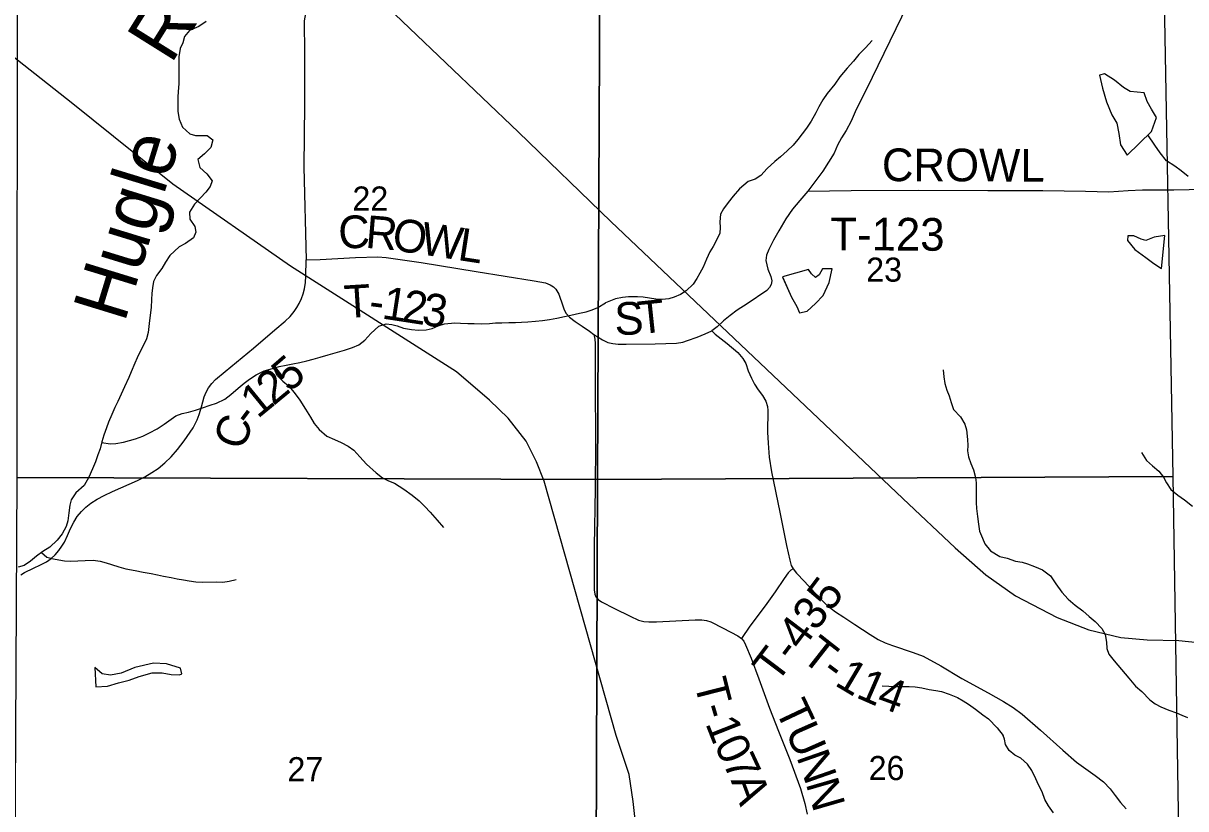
# Model space of a CAD drawing. Extents: x 0 to 34, y 0 to 22.
# Drawn here: x 3.267 to 5.287, y 18.409 to 19.775 of the extents above; entities that cross this region are included whole.
import ezdxf

# ---------------------------------------------------------------- set-up
doc = ezdxf.new("R2010")
doc.units = 0
doc.layers.add('Default', color=7, linetype='Continuous')

msp = doc.modelspace()

# ---------------------------------------------------------------- linework, layer by layer
at = {"layer": 'Default'}
for points in [[(2.781, 20.587), (3.2581, 20.2961), (3.5691, 20.1012), (3.6469, 20.0395), (3.6858, 20.0076), (4.1277, 19.5854), (4.2882, 19.4298), (4.7959, 18.9483), (4.8867, 18.8627), (4.9397, 18.8161), (4.9914, 18.7791), (5.0638, 18.7415), (5.1188, 18.7201), (5.1744, 18.7071), (5.2205, 18.7028), (5.2754, 18.7016), (5.3374, 18.6952), (5.4602, 18.6836), (5.597, 18.6827), (5.698, 18.6656), (5.9841, 18.6456), (6.1617, 18.6371), (6.2768, 18.6314)], [(3.7949, 19.8708), (3.7793, 19.8505), (3.7736, 19.8419), (3.7693, 19.8339), (3.7648, 19.8223), (3.7614, 19.8101), (3.7555, 19.779), (3.7561, 19.722), (3.7559, 19.6337), (3.7546, 19.5245), (3.759, 19.3634)], [(4.8036, 19.8068), (4.732, 19.6587), (4.7148, 19.6248), (4.7062, 19.6042), (4.6971, 19.5879), (4.6892, 19.5753), (4.6821, 19.5627), (4.6765, 19.549), (4.6569, 19.5177), (4.6426, 19.4987), (4.6308, 19.4826)], [(3.5852, 19.7778), (3.5721, 19.7689), (3.5562, 19.7618), (3.5473, 19.7514), (3.5444, 19.7407), (3.5396, 19.7304), (3.5375, 19.7163), (3.5373, 19.7053), (3.5378, 19.6939), (3.5376, 19.6825), (3.5374, 19.6692), (3.5361, 19.6559), (3.5359, 19.646), (3.5356, 19.635), (3.5358, 19.6213), (3.5383, 19.6077), (3.5438, 19.5937), (3.5565, 19.5825), (3.5664, 19.5796), (3.5766, 19.5794), (3.5865, 19.5795), (3.5968, 19.5717), (3.5932, 19.5587), (3.582, 19.5475), (3.5707, 19.5375), (3.5743, 19.5239), (3.5862, 19.513), (3.5955, 19.5006), (3.5922, 19.4907), (3.5844, 19.4807), (3.5751, 19.4711), (3.565, 19.4603), (3.5561, 19.4465)], [(4.3327, 18.3689), (4.327, 18.4219), (4.32, 18.469), (4.2976, 18.5366), (4.1726, 18.9789), (4.1592, 19.0123), (4.141, 19.0483), (4.1098, 19.0881), (4.0777, 19.1194), (4.02, 19.1687), (3.7318, 19.3523), (3.5272, 19.4951), (3.3531, 19.6346), (3.2123, 19.745)], [(4.7427, 19.7448), (4.7311, 19.7317), (4.7192, 19.7201), (4.7099, 19.7085), (4.6987, 19.6965), (4.6864, 19.6814), (4.6775, 19.6687), (4.6642, 19.6525), (4.6568, 19.6413), (4.6498, 19.6294), (4.6446, 19.6191), (4.6362, 19.6041), (4.6284, 19.5921), (4.6206, 19.5821), (4.6132, 19.5725), (4.605, 19.5628), (4.5949, 19.5531), (4.583, 19.5422), (4.5732, 19.5341), (4.5598, 19.522), (4.549, 19.51), (4.5392, 19.5038), (4.5267, 19.4997), (4.5121, 19.4869), (4.501, 19.4738), (4.4924, 19.4633), (4.4843, 19.4522), (4.4791, 19.4426), (4.4775, 19.4292), (4.4784, 19.4194), (4.4775, 19.4095), (4.472, 19.3976), (4.4661, 19.3868), (4.4602, 19.3772), (4.4544, 19.3646), (4.4486, 19.3508), (4.4431, 19.3404), (4.4379, 19.3308), (4.4316, 19.3208), (4.4193, 19.3095), (4.4092, 19.3029), (4.3986, 19.2985), (4.3888, 19.2956), (4.3774, 19.2947), (4.3663, 19.2952), (4.3553, 19.2969), (4.3442, 19.2982), (4.3347, 19.2988), (4.3191, 19.2992), (4.3084, 19.2979), (4.2963, 19.2954), (4.2792, 19.2885)], [(5.2277, 19.5867), (5.2368, 19.6105), (5.2278, 19.6251), (5.2206, 19.6387), (5.215, 19.6538), (5.191, 19.6559), (5.1791, 19.6629), (5.1633, 19.6755), (5.1459, 19.6866), (5.1376, 19.6845), (5.143, 19.6618), (5.1495, 19.638), (5.1587, 19.6154), (5.1674, 19.6011), (5.1711, 19.583), (5.1738, 19.5633), (5.1856, 19.5453)], [(5.1856, 19.5453), (5.2277, 19.5867)], [(5.2916, 19.5082), (5.2797, 19.5178), (5.2685, 19.526), (5.2542, 19.5356), (5.2429, 19.5494), (5.2339, 19.5629), (5.2217, 19.5808)], [(4.6308, 19.4826), (4.7057, 19.484), (4.8231, 19.4843), (4.9433, 19.4838), (5.0389, 19.4839), (5.113, 19.483), (5.1538, 19.4816), (5.1871, 19.4836), (5.2124, 19.4853), (5.2667, 19.4853), (5.346, 19.4867), (5.3931, 19.4869), (5.4678, 19.4898), (5.5083, 19.4915), (5.5457, 19.4927), (5.5977, 19.493), (5.701, 19.4923), (5.8241, 19.4952), (5.8521, 19.4965), (5.9483, 19.4963), (5.9584, 19.4952)], [(4.6308, 19.4826), (4.6168, 19.4665), (4.6041, 19.4516), (4.5922, 19.4347), (4.58, 19.414), (4.5707, 19.3974), (4.563, 19.3816), (4.5588, 19.3717), (4.5574, 19.3621), (4.5609, 19.3474), (4.5666, 19.3343), (4.568, 19.327), (4.5671, 19.3207), (4.5643, 19.3153), (4.5595, 19.3102), (4.5253, 19.2871), (4.5081, 19.2757), (4.4958, 19.2666), (4.4842, 19.2572), (4.473, 19.2467), (4.464, 19.2398)], [(3.5561, 19.4465), (3.5566, 19.4343), (3.5655, 19.4211), (3.5672, 19.4113), (3.5628, 19.4017), (3.5489, 19.392), (3.5383, 19.3858), (3.5219, 19.3711), (3.5141, 19.3592), (3.5078, 19.3485), (3.4988, 19.3362), (3.4937, 19.3255), (3.4915, 19.3149), (3.4909, 19.3046), (3.4903, 19.2947), (3.4894, 19.2803), (3.4877, 19.2669), (3.486, 19.2525), (3.4843, 19.2369), (3.4814, 19.2258), (3.4763, 19.2151), (3.4707, 19.2051), (3.4652, 19.1933), (3.4608, 19.1837), (3.4549, 19.1688), (3.4509, 19.1589), (3.4431, 19.1424), (3.4314, 19.1172), (3.4262, 19.1069), (3.4211, 19.0946), (3.4155, 19.0813), (3.4119, 19.0713), (3.4075, 19.0587), (3.4039, 19.0469), (3.401, 19.0351), (3.3966, 19.0244), (3.393, 19.0122), (3.3875, 18.9999), (3.3809, 18.9854), (3.3731, 18.9712), (3.3585, 18.9585), (3.3507, 18.9462), (3.3482, 18.9367), (3.3465, 18.9237), (3.3447, 18.91), (3.3419, 18.8997), (3.3348, 18.8871), (3.3259, 18.876), (3.3132, 18.864), (3.3011, 18.8562), (3.2902, 18.8485), (3.2797, 18.8396), (3.2685, 18.8318), (3.2583, 18.8294)], [(5.251, 19.4056), (5.2324, 19.4029), (5.2181, 19.3969), (5.2097, 19.3994), (5.197, 19.4049), (5.1867, 19.4051), (5.1861, 19.3971), (5.199, 19.3814), (5.2183, 19.3677), (5.2322, 19.3569), (5.2453, 19.3481)], [(5.2453, 19.3481), (5.251, 19.4056)], [(3.2631, 18.816), (3.2692, 18.8197), (3.2847, 18.8274), (3.2974, 18.8331), (3.3075, 18.8384), (3.3155, 18.8442), (3.3226, 18.8509), (3.3292, 18.8582), (3.3344, 18.8656), (3.3386, 18.8729), (3.3443, 18.8843), (3.3493, 18.8962), (3.3548, 18.9074), (3.361, 18.9173), (3.3684, 18.926), (3.3761, 18.9334), (3.3849, 18.9403), (3.3958, 18.9473), (3.4078, 18.9539), (3.4222, 18.9608), (3.4656, 18.98), (3.4783, 18.9864), (3.4907, 18.9935), (3.5016, 19.0009), (3.5135, 19.0104), (3.5244, 19.0207), (3.5354, 19.0335), (3.5469, 19.0489), (3.557, 19.0636), (3.5622, 19.0715), (3.566, 19.0782), (3.5693, 19.0854), (3.5729, 19.0947), (3.5768, 19.1078), (3.5818, 19.1254), (3.5851, 19.1335), (3.589, 19.1408), (3.5947, 19.1486), (3.6012, 19.1552), (3.6182, 19.1694), (3.6671, 19.2099), (3.7044, 19.2416), (3.7223, 19.2567), (3.7309, 19.2651), (3.7379, 19.2736), (3.7424, 19.2804), (3.7465, 19.2872), (3.7507, 19.296), (3.7537, 19.3044), (3.7559, 19.3127), (3.7578, 19.3237), (3.7585, 19.3351), (3.759, 19.3634)], [(3.759, 19.3634), (3.7832, 19.3638), (3.8443, 19.3673), (3.8834, 19.3683), (3.8981, 19.3675), (3.9588, 19.3587), (4.0545, 19.3432), (4.1551, 19.327), (4.1747, 19.3234), (4.1829, 19.3202), (4.1884, 19.3167), (4.1925, 19.3122), (4.1977, 19.3034), (4.2046, 19.2832), (4.2071, 19.2765), (4.2106, 19.2702), (4.2162, 19.2636), (4.2262, 19.2561), (4.2384, 19.2482), (4.2513, 19.2391), (4.2585, 19.2338), (4.274, 19.2244), (4.2831, 19.2199), (4.2916, 19.2177), (4.3012, 19.2168), (4.3147, 19.2166), (4.3654, 19.2173), (4.4023, 19.2186), (4.4132, 19.2204), (4.4218, 19.2229), (4.4382, 19.2287), (4.4523, 19.2349), (4.464, 19.2398)], [(4.5867, 19.3337), (4.6021, 19.2987), (4.6116, 19.2825), (4.6164, 19.2712), (4.6292, 19.2741), (4.6442, 19.2873), (4.6572, 19.3016), (4.6679, 19.3239), (4.6727, 19.3475), (4.6564, 19.3476), (4.6505, 19.3372), (4.6437, 19.3329), (4.6371, 19.3392), (4.632, 19.3467)], [(4.632, 19.3467), (4.5867, 19.3337)], [(4.587, 19.3322), (4.6021, 19.2987), (4.6116, 19.2825), (4.6164, 19.2712), (4.6292, 19.2741), (4.6442, 19.2873), (4.6572, 19.3016), (4.6679, 19.3239), (4.6727, 19.3475), (4.6564, 19.3476), (4.6505, 19.3372), (4.6437, 19.3329), (4.6371, 19.3392), (4.632, 19.3467)], [(3.4036, 19.0458), (3.4183, 19.0437), (3.4278, 19.0442), (3.4414, 19.0467), (3.4516, 19.0491), (3.4622, 19.0523), (3.475, 19.057), (3.4863, 19.0625), (3.4999, 19.0699), (3.5123, 19.0777), (3.5322, 19.0924), (3.5435, 19.096), (3.5545, 19.0984), (3.5666, 19.102), (3.5786, 19.106), (3.5919, 19.1108), (3.6028, 19.1143), (3.6175, 19.121), (3.628, 19.1295), (3.6407, 19.1403), (3.6509, 19.1488), (3.6606, 19.1558), (3.6719, 19.1632), (3.6858, 19.1702), (3.7006, 19.1746), (3.7119, 19.1778), (3.724, 19.1803), (3.7357, 19.1827), (3.7478, 19.1852), (3.7599, 19.188), (3.7712, 19.1908), (3.7829, 19.1944), (3.7973, 19.1984), (3.8253, 19.2064), (3.8396, 19.2112), (3.8501, 19.2159), (3.861, 19.2236), (3.8711, 19.2356), (3.8854, 19.2479), (3.8978, 19.2523), (3.9077, 19.2509), (3.9172, 19.2484), (3.9282, 19.2447), (3.9419, 19.2423), (3.9541, 19.2409), (3.9673, 19.2419), (3.9779, 19.2443), (3.9881, 19.2486), (3.9994, 19.2522), (4.0169, 19.254), (4.0271, 19.2534), (4.0396, 19.2528), (4.0506, 19.2526), (4.0643, 19.2524), (4.0772, 19.2526), (4.0881, 19.2539), (4.0988, 19.254), (4.1113, 19.2546), (4.1226, 19.2547), (4.1333, 19.2549), (4.1439, 19.2558), (4.1575, 19.2567), (4.1696, 19.2581), (4.1817, 19.2598), (4.1946, 19.2618), (4.2078, 19.2647), (4.2188, 19.2671), (4.2339, 19.2704), (4.2453, 19.2732), (4.2558, 19.2764), (4.2656, 19.2803), (4.2792, 19.2885)], [(4.2585, 19.2338), (4.2605, 19.2253), (4.2612, 19.2178), (4.2611, 19.2033), (4.2608, 19.1505), (4.2615, 19.0451), (4.2608, 18.9653), (4.2593, 18.8656), (4.2591, 18.7896), (4.2603, 18.7824), (4.2623, 18.7775), (4.2661, 18.7731), (4.2721, 18.7689), (4.2948, 18.7572), (4.3221, 18.7438), (4.3362, 18.7373), (4.3459, 18.7348), (4.3545, 18.7339), (4.3678, 18.7341), (4.4351, 18.7378), (4.4464, 18.7377), (4.4547, 18.7364), (4.4623, 18.7339), (4.4834, 18.7231), (4.5091, 18.7098), (4.5154, 18.7054), (4.5193, 18.7003), (4.5225, 18.694), (4.532, 18.671), (4.5454, 18.635), (4.5643, 18.584), (4.5797, 18.5444), (4.5996, 18.4947), (4.6178, 18.4443), (4.6255, 18.4186), (4.6295, 18.3999)], [(4.464, 19.2398), (4.4696, 19.2341), (4.4904, 19.2178), (4.509, 19.2023), (4.5179, 19.1921), (4.5231, 19.1834), (4.5271, 19.1706), (4.5327, 19.1574), (4.5378, 19.1473), (4.5441, 19.1372), (4.5517, 19.1278), (4.5577, 19.1176), (4.5604, 19.1086), (4.5611, 19.1012), (4.5606, 19.0637), (4.5616, 19.0449), (4.5635, 19.0203), (4.5677, 18.9947), (4.5818, 18.9249), (4.5935, 18.8668), (4.5992, 18.8415), (4.6016, 18.8322), (4.6049, 18.8261), (4.6109, 18.819), (4.6246, 18.8041), (4.6492, 18.7774), (4.6639, 18.7634), (4.679, 18.7517), (4.6934, 18.7422), (4.7125, 18.7298), (4.7387, 18.7121), (4.753, 18.7034), (4.7649, 18.6976), (4.7777, 18.6929), (4.8137, 18.681), (4.8308, 18.6744), (4.8618, 18.6575), (4.8984, 18.6358), (4.944, 18.6108), (4.9705, 18.5958), (4.9873, 18.5854), (5.0031, 18.5738), (5.0351, 18.5461), (5.0739, 18.5111), (5.0975, 18.4903), (5.1299, 18.4671), (5.1444, 18.4561), (5.1558, 18.4438), (5.1646, 18.4325), (5.1741, 18.42), (5.184, 18.4092)], [(3.7027, 19.1752), (3.7079, 19.1629), (3.7183, 19.1525), (3.7279, 19.1446), (3.7379, 19.133), (3.7476, 19.1194), (3.7577, 19.104), (3.7662, 19.0901), (3.7728, 19.0791), (3.7817, 19.0683), (3.7947, 19.0567), (3.8081, 19.0512), (3.8199, 19.046), (3.8317, 19.0397), (3.8417, 19.0323), (3.8521, 19.021), (3.8637, 19.0083), (3.8806, 18.9929), (3.8917, 18.9847), (3.902, 18.9792), (3.9123, 18.9751), (3.9287, 18.9647), (3.9433, 18.9543), (3.9552, 18.9446), (3.9648, 18.9349), (3.9744, 18.9247), (3.9867, 18.9109), (3.9972, 18.8981)], [(4.8656, 19.1723), (4.8669, 19.1598), (4.8687, 19.1485), (4.8723, 19.1368), (4.876, 19.1269), (4.88, 19.1156), (4.884, 19.1035), (4.8961, 19.0905), (4.9032, 19.0777), (4.9064, 19.0679), (4.9082, 19.0512), (4.9084, 19.0409), (4.9082, 19.0314), (4.91, 19.0212), (4.914, 19.0095), (4.9184, 18.9986), (4.9221, 18.985), (4.9234, 18.9755), (4.9232, 18.9637), (4.9231, 18.9516), (4.9229, 18.9417), (4.9235, 18.931), (4.9257, 18.9174), (4.9274, 18.9041), (4.9292, 18.892), (4.934, 18.8796), (4.938, 18.8698), (4.9481, 18.8578), (4.9643, 18.8479), (4.9769, 18.8447), (4.9918, 18.8397), (5.0029, 18.8376), (5.0125, 18.8347), (5.0243, 18.8304), (5.0385, 18.8246), (5.0521, 18.8139), (5.0615, 18.8), (5.072, 18.7858), (5.0829, 18.7734), (5.0953, 18.7634), (5.1084, 18.7534), (5.1196, 18.7434), (5.1297, 18.7348), (5.1417, 18.7225), (5.1472, 18.712), (5.1494, 18.6991), (5.15, 18.6881), (5.154, 18.6779), (5.163, 18.6663), (5.1758, 18.6514), (5.1883, 18.636), (5.1999, 18.6226), (5.2112, 18.6129), (5.2248, 18.5984), (5.2344, 18.5917), (5.244, 18.5862), (5.2578, 18.5808), (5.2712, 18.5761), (5.2808, 18.5721), (5.2904, 18.5677)], [(5.2104, 19.0282), (5.219, 19.0143), (5.2298, 19.0054), (5.2407, 18.9961), (5.2489, 18.9856), (5.254, 18.9755), (5.2614, 18.9642), (5.2734, 18.9542), (5.285, 18.9461), (5.2993, 18.9353)], [(3.2989, 18.8546), (3.3081, 18.8465), (3.3195, 18.8436), (3.329, 18.8422), (3.3389, 18.8404), (3.3491, 18.8394), (3.362, 18.84), (3.3749, 18.841), (3.3889, 18.8412), (3.4007, 18.8394), (3.411, 18.8369), (3.4205, 18.834), (3.4331, 18.8296), (3.4456, 18.8264), (3.4616, 18.8232), (3.4753, 18.8207), (3.4894, 18.8183), (3.5004, 18.8158), (3.5107, 18.8136), (3.5244, 18.8112), (3.5346, 18.809), (3.5457, 18.8069), (3.5555, 18.8052), (3.5673, 18.8038), (3.5795, 18.8032), (3.6033, 18.8036), (3.6143, 18.8033), (3.6249, 18.8046), (3.637, 18.8078)], [(4.6049, 18.8261), (4.6012, 18.8239), (4.5965, 18.8191), (4.5896, 18.8094), (4.5736, 18.7863), (4.5564, 18.762), (4.5299, 18.7269), (4.5154, 18.7054)], [(3.3935, 18.6209), (3.4136, 18.6223), (3.4329, 18.6279), (3.451, 18.6327), (3.4687, 18.639), (3.491, 18.6454), (3.5088, 18.6453), (3.5241, 18.6425), (3.5385, 18.6419), (3.5426, 18.6435), (3.5402, 18.6537), (3.5162, 18.6614), (3.4934, 18.6626), (3.4613, 18.6549), (3.4372, 18.6447), (3.4186, 18.6414), (3.4046, 18.6438), (3.3915, 18.6547)], [(3.3915, 18.6547), (3.3935, 18.6209)], [(4.7601, 18.6231), (4.7716, 18.6226), (4.7819, 18.6216), (4.7944, 18.6219), (4.8066, 18.6217), (4.8172, 18.6212), (4.8287, 18.6195), (4.8417, 18.6163), (4.8531, 18.615), (4.8631, 18.613), (4.8765, 18.6087), (4.8906, 18.6029), (4.9003, 18.5966), (4.9099, 18.5911), (4.9222, 18.5822), (4.935, 18.5726), (4.9446, 18.5655), (4.9594, 18.5499), (4.9703, 18.5368)], [(5.0577, 18.4022), (5.0489, 18.4143), (5.0423, 18.4252), (5.0376, 18.4385), (5.0317, 18.451), (5.0267, 18.4612), (5.0201, 18.4755), (5.0123, 18.4865), (5.0008, 18.497), (4.9901, 18.5026), (4.9805, 18.5105), (4.9743, 18.5207), (4.9723, 18.5302), (4.9703, 18.5368)]]:
    msp.add_lwpolyline(points, dxfattribs=at)
for points in [[(4.2696, 19.9768), (4.2649, 18.9814), (3.2565, 18.9852), (3.2572, 19.9844)], [(4.2696, 19.9768), (5.2472, 19.9737), (5.2648, 18.9869), (4.2649, 18.9814)], [(3.2565, 18.9852), (4.2649, 18.9814), (4.2617, 17.9979), (3.2516, 17.9922)], [(4.2649, 18.9814), (5.2648, 18.9869), (5.2805, 18.0037), (4.2617, 17.9979)]]:
    msp.add_lwpolyline(points, close=True, dxfattribs=at)

# ---------------------------------------------------------------- texts
for s, height, rotation, p in [('Run', 0.09471, 57.9525, (3.5238, 19.7017)), ('Hugle', 0.09471, 72.9454, (3.443, 19.2524)), ('CROWL', 0.05682, 359.8098, (4.7593, 19.5002)), ('22', 0.04186, 0, (3.8392, 19.449)), ('C', 0.0568, 2.1744, (3.8157, 19.3826)), ('R', 0.0568, 355.2642, (3.8606, 19.3844)), ('O', 0.0568, 351.4696, (3.9061, 19.3807)), ('T-123', 0.05682, 359.7141, (4.6696, 19.3801)), ('W', 0.0568, 351.2681, (3.9555, 19.3733)), ('L', 0.0568, 351.2662, (4.0206, 19.3633)), ('23', 0.04186, 0, (4.7321, 19.3254)), ('T', 0.0568, 3.5036, (3.8264, 19.2619)), ('1', 0.0568, 351.2803, (3.8888, 19.2616)), ('2', 0.0568, 351.2649, (3.9233, 19.2563)), ('3', 0.0568, 351.2443, (3.9579, 19.251)), ('T', 0.0568, 6.0499, (4.3382, 19.234)), ('-', 0.0568, 352.5168, (3.8659, 19.2646)), ('S', 0.0568, 1.8962, (4.2954, 19.2324)), ('5', 0.0568, 40.7949, (3.7297, 19.1317)), ('2', 0.0568, 39.6434, (3.7018, 19.1086)), ('1', 0.0568, 39.2685, (3.6744, 19.0862)), ('C', 0.0568, 71.3528, (3.6501, 19.0302)), ('-', 0.0568, 52.9568, (3.6628, 19.0701)), ('T-435', 0.05682, 52.9612, (4.5762, 18.6251)), ('T', 0.0568, 321.9198, (4.6165, 18.6695)), ('-', 0.0568, 323.425, (4.6513, 18.6423)), ('1', 0.0568, 329.2873, (4.6753, 18.6249)), ('1', 0.0568, 336.4542, (4.7123, 18.6035)), ('T', 0.0568, 284.2369, (4.4326, 18.6288)), ('4', 0.0568, 340.0356, (4.7479, 18.5881)), ('-', 0.0568, 286.2054, (4.4436, 18.5856)), ('T', 0.0568, 295.2924, (4.5727, 18.5824)), ('1', 0.0568, 291.5135, (4.452, 18.5577)), ('U', 0.0568, 293.8271, (4.5907, 18.5443)), ('0', 0.0568, 295.9463, (4.4667, 18.5208)), ('7', 0.0568, 294.8682, (4.4819, 18.4896)), ('N', 0.0568, 289.3208, (4.6105, 18.4997)), ('27', 0.04186, 0, (3.7263, 18.4571)), ('26', 0.04186, 0, (4.7363, 18.4591)), ('A', 0.0568, 290.3429, (4.4962, 18.4589)), ('N', 0.0568, 286.1385, (4.6268, 18.4533))]:
    msp.add_text(s, height=height, rotation=rotation, dxfattribs=at).set_placement(p)

doc.saveas('drawing.dxf')
